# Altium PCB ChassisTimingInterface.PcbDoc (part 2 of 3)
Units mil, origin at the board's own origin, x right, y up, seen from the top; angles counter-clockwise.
Board outline 3400 x 6000 mil, 8 copper layers (Top Layer, GND, VDD, Mid-Layer 1, VCCAUX, Mid-Layer 2, MidLayer3, Bottom Layer), stack 62.1 mil thick; 229 components, 254 nets, 1249 pads, 708 vias.
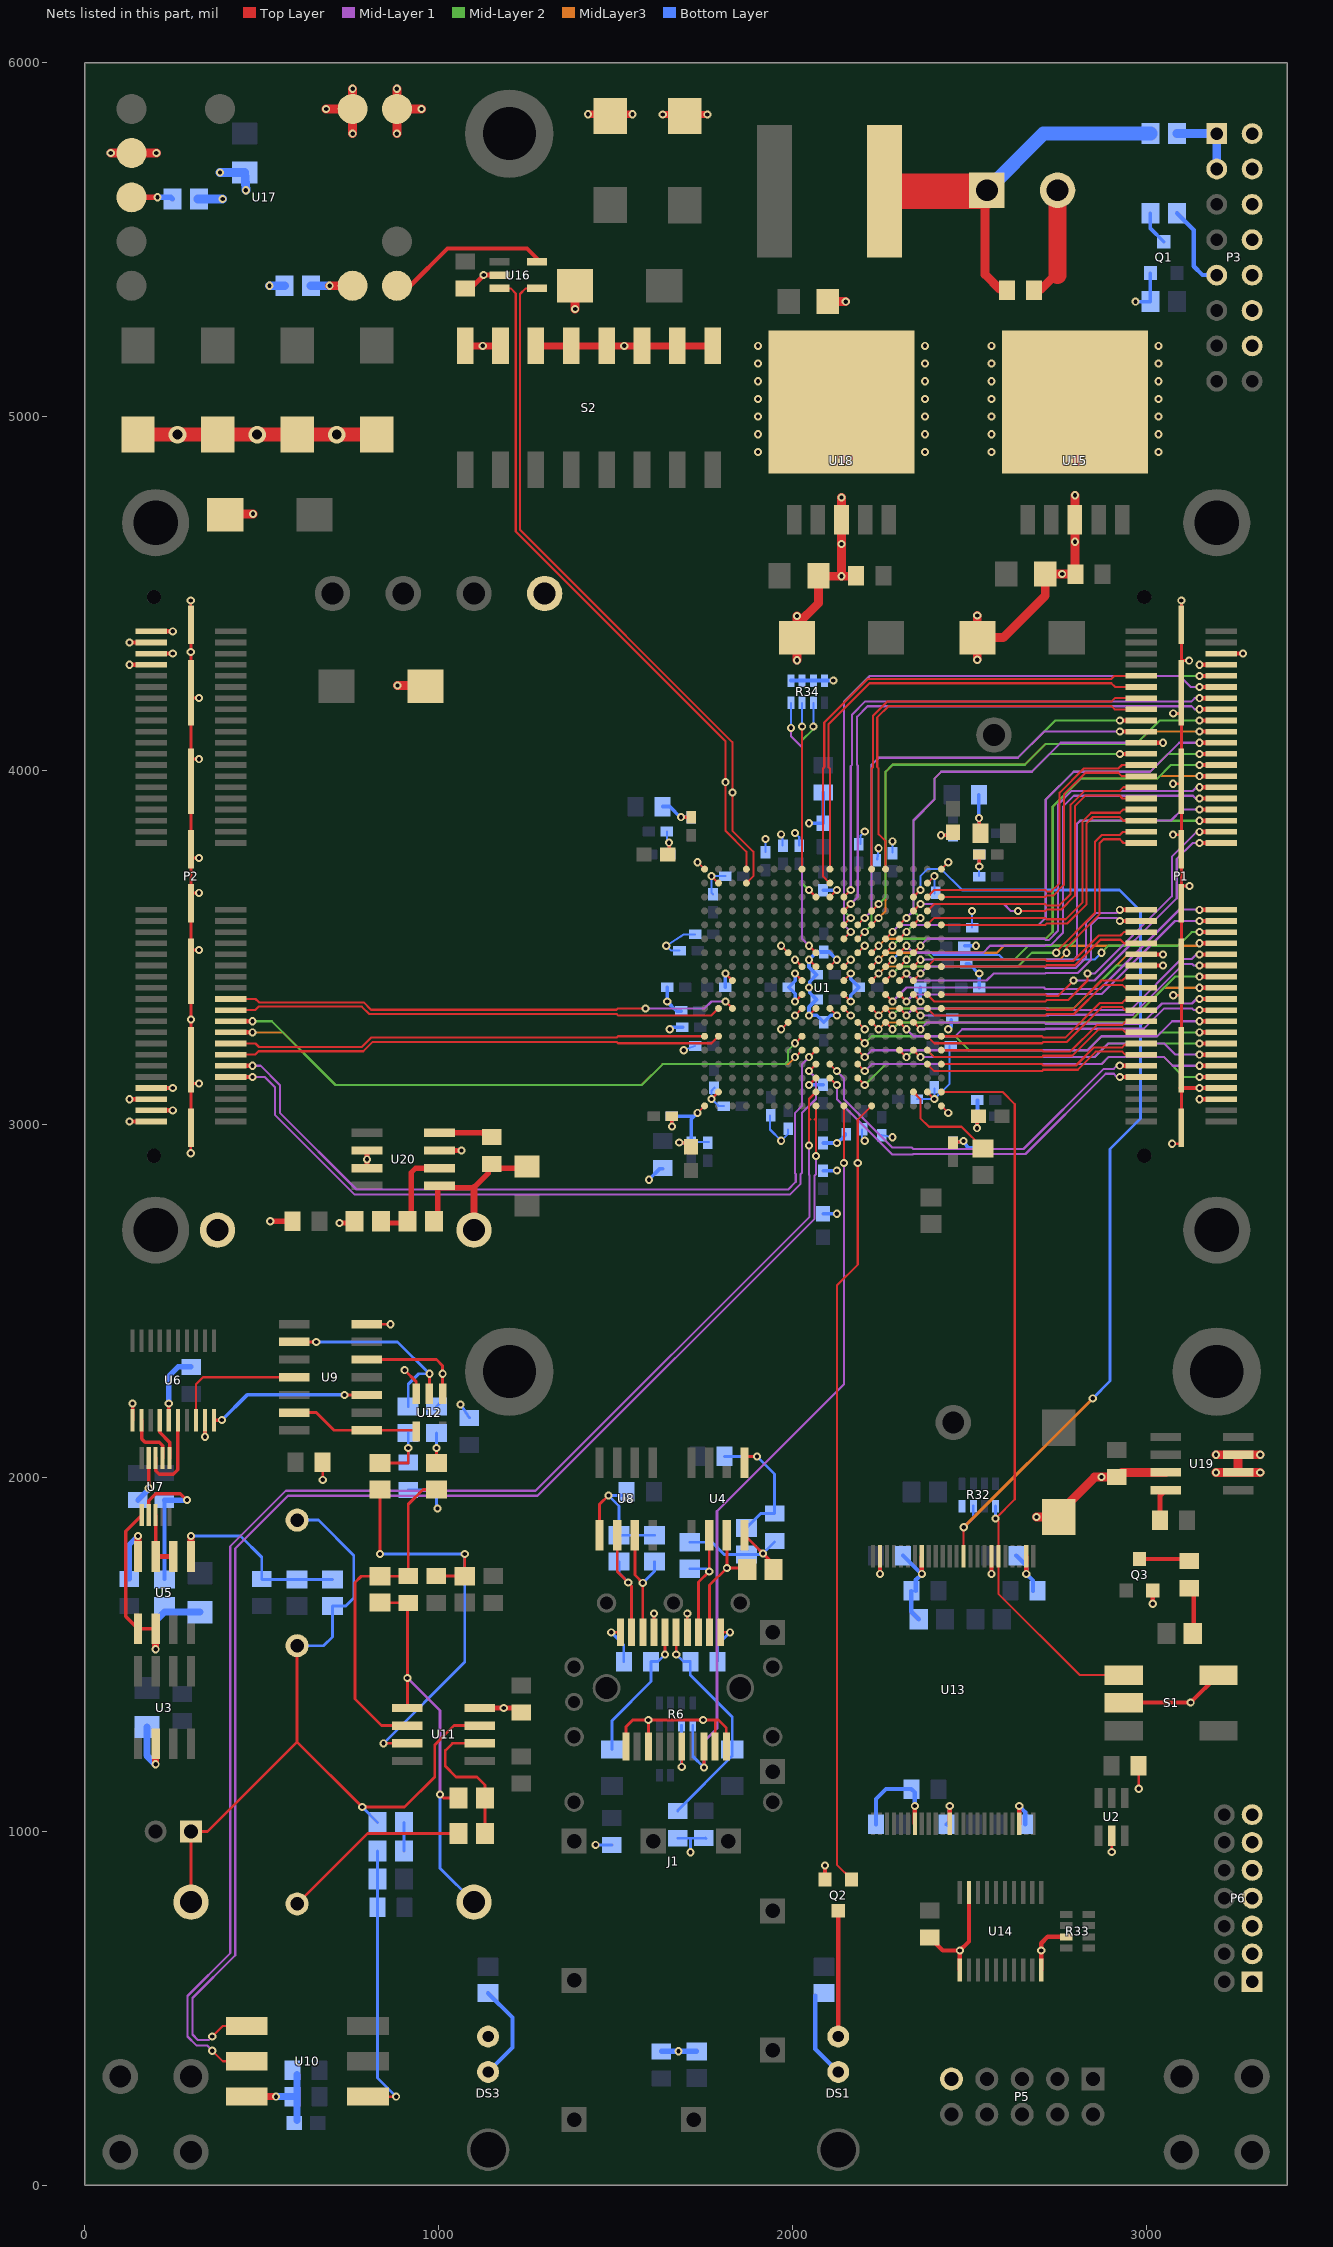
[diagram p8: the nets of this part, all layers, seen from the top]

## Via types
v1: diameter 23, hole 12, Top Layer to Bottom Layer, 669 vias
v2: diameter 23, hole 12.01, Top Layer to Bottom Layer, 33 vias
v3: diameter 50, hole 28, Top Layer to Bottom Layer, 6 vias

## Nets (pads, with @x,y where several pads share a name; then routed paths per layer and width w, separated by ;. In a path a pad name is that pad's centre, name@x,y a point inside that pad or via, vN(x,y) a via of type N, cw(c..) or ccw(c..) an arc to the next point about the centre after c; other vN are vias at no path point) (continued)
GND: C1.1 C4.1 C6.1 C7.1 C8.1 C9.1 C11.2 C12.1 C19.2 C21.1 C26.2 C27.2 C28.2 C29.2 C30.1 C31.1 C32.2 C33.1 C34.1 C35.1 C36.1 C37.1 C38.1 C39.1 C40.1 C41.2 C42.1 C43.1 C44.2 C45.2 C46.2 C47.2 C48.1 C49.2 C50.2 C51.2 C52.2 C53.2 C54.2 C55.1 C56.1 C57.2 C59.1 C62.1 C63.2 C64.2 C65.2 C66.2 C67.2 C68.2 C69.2 C70.2 C71.2 C72.2 C73.2 C74.1 C75.1 C76.1 C77.1 C78.1 C79.1 C80.1 C81.1 C82.1 C83.1 C84.1 C85.1 C86.1 C87.1 C88.1 C89.1 C90.1 C91.1 C92.1 C93.1 C94.1 C95.1 C96.1 C97.1 C98.1 C99.1 C100.1 C101.1 C102.1 C103.1 C104.1 C105.1 C106.1 C107.1 C108.1 C109.1 C110.1 C111.1 C112.1 C113.1 C114.1 C115.1 C116.1 C117.1 C118.1 C119.1 C120.1 C121.1 C122.1 C123.1 C124.1 C125.1 C126.1 C127.1 C128.1 C129.1 C130.1 C131.1 C132.1 C133.1 C134.1 C135.1 C136.1 DS3.1 J1.1 J1.3 J1.9 J1.10 J1.11 J1.14 J1.17 J1.20 P1.5 P1.7 P1.73 P1.75 P1.81 P1.82 P1.83 P1.84 P1.85 P1.86 P1.87 P1.88 P2.2 P2.4 P2.6 P2.8 P2.74 P2.76 P2.78 P2.80 P2.81 P2.82 P2.83 P2.84 P2.85 P2.86 P2.87 P2.88 P3.2 P3.4 P3.6 P3.8 P3.10 P3.12 P3.14 P5.9 P6.1 P6.3 P6.5 P6.7 P6.9 P6.11 P6.13 P7.2 Q1.2 Q2.2 Q3.2 R4.1 R8.2 R11.2 R13.1 R14.2 R30.2 R33.3 R34.5 R34.6 R34.7 R34.8 R37.1 R38.2 R40.2 S1.2 S1.5 S2.9 S2.10 S2.11 S2.12 S2.13 S2.14 S2.15 S2.16 TP9.1 TP10.1 U1.A1 U1.A18 U1.B2 U1.B17 U1.C10 U1.G7 U1.G12 U1.H8 U1.H9 U1.H10 U1.H11 U1.J3 U1.J8 U1.J11 U1.K8 U1.K11 U1.K16 U1.L8 U1.L9 U1.L10 U1.L11 U1.M7 U1.M12 U1.T9 U1.U2 U1.U17 U1.V1 U1.V18 U2.2 U4.5 U6.11 U6.15 U6.19 U7.9 U8.5 U9.7 U12.3 U13.2 U13.7 U13.17 U13.23 U13.31 U13.36 U13.46 U14.1 U14.10 U14.19 U15.3 U16.2 U17.3 U17.4 U17.7 U18.3 U19.3 U19.6 U19.7 U20.3 U20.6 U20.7 | length 18447.6
  Top Layer w6: v1(1732.3,3031.5) U1.A18@1751.99,3051.18 ; v1(1732.3,3740.16) U1.V18@1751.99,3720.47 ; v1(1771.67,3070.87) U1.B17@1791.36,3090.55 ; v1(1771.67,3700.79) U1.U17@1791.36,3681.1 ; v1(1811.04,3425.2) U1.K16@1830.73,3405.51 ; v1(1968.52,3267.72) U1.G12@1988.21,3287.4 ; v1(1968.52,3503.94) U1.M12@1988.21,3484.25 ; v1(2007.89,3307.09) U1.H11@2027.58,3326.77 ; v1(2007.89,3346.46) U1.J11@2027.58,3366.14 ; v1(2007.89,3425.2) U1.K11@2027.58,3405.51 ; v1(2007.89,3464.57) U1.L11@2027.58,3444.88 ; v1(2047.26,3110.24) U1.C10@2066.95,3129.92 ; v1(2047.26,3307.09) U1.H10@2066.95,3326.77 ; v1(2047.26,3464.57) U1.L10@2066.95,3444.88 ; U1.H9@2106.32,3326.77 v1(2126,3307.09) ; U1.L9@2106.32,3444.88 v1(2126,3464.57) ; U1.T9@2106.32,3641.73 v1(2126,3661.42) ; U1.H8@2145.69,3326.77 v1(2165.37,3307.09) ; U1.J8@2145.69,3366.14 v1(2165.37,3346.46) ; U1.K8@2145.69,3405.51 v1(2165.37,3425.2) ; U1.L8@2145.69,3444.88 v1(2165.37,3464.57) ; U1.G7@2185.06,3287.4 v1(2204.74,3267.72) ; U1.M7@2185.06,3484.25 v1(2204.74,3503.94) ; U1.J3@2342.54,3366.14 v1(2362.22,3346.46) ; U1.B2@2381.91,3090.55 v1(2401.59,3070.87) ; U1.U2@2381.91,3681.1 v1(2401.59,3700.79) ; U1.A1@2421.28,3051.18 v1(2440.96,3031.5) ; U1.V1@2421.28,3720.47 v1(2440.96,3740.16)
  Top Layer w8: v1(299.21,2917.32) P2.81@299.21,2988 ; v1(299.21,4480.31) 299.21,4412 P2.88@300,4411.22 P2.81@300,2988.78 ; P2.82@300,3114.17 v1(322.83,3114.17) ; P2.83@300,3492.13 v1(322.83,3492.13) ; P2.84@300,3653.54 v1(322.83,3653.54) ; P2.85@300,3751.97 v1(322.83,3751.97) ; P2.86@300,4031.5 v1(322.83,4031.5) ; P2.87@300,4204.72 v1(322.83,4204.72) ; v1(672.39,1994) C30.1@672.4,2044.02 ; U9.7@796.36,2434 v1(864,2434) ; v1(904,2304) 936.6,2271.4 U12.3@936.6,2237.15 ; U8.5@1455,1837.64 1455,1925 v1(1480,1950) ; v1(1488.17,1562.83) J1.20@1514.25,1562.83 ; J1.1@1530,1240 1530,1296 1549,1315 1791,1315 1813.46,1292.54 J1.10@1813.46,1240 ; J1.3@1592.99,1240 v1@1592.99,1312.99 ; J1.17@1608.74,1562.83 v1(1608.74,1616.26) ; J1.14@1703.23,1562.83 v1(1703.23,1615.77) ; J1.9@1781.97,1240 1781.97,1313.03 ; J1.11@1797.72,1562.83 v1(1824.17,1562.83) ; U4.5@1860,2060 v1(1900,2060) ; U2.2@2902.26,987.89 v1(2903,942) ; v1(2979.39,1120.61) C1.1@2979.39,1185 ; v1(3074,2944) 3098.53,2944 P1.81@3099.41,2944.88 ; v1(3076,3818) 3098,3818 3100,3820 3100,3960 3098,3962 v1(3076,3962) ; v1(3077,3364) 3099,3364 3100,3365 P1.82@3100,3181.3 ; v1(3077,4161) 3099,4161 3100,4160 P1.86@3100,3968.7 ; P1.81@3100,2988.78 3100,3046 ; 3100,3047 P1.82@3100,3100 ; P1.83@3100,3431.3 P1.84@3100,3623.83 ; P1.85@3100,3776.17 3100,3675 3102,3673 v1(3123,3673) ; P1.87@3100,4218.7 v1(3100,4480) ; P1.87@3100,4310 v1(3122,4310)
  Top Layer w10: U6.11@134.84,2162.8 v2(134.84,2209.84) ; v2(180.32,1970.31) U7.9@180.32,2055.71 ; U6.15@237.2,2162.8 v2(237.2,2209.84) ; v2(339.57,2115.75) U6.19@339.57,2162.8 ; C117.1@1647.52,3761.88 1651.65,3766.01 v1(1651.65,3795.47) ; v1(1659.65,2993.29) C116.1@1659.65,3021.88 ; v1(1680.47,2947.47) 1701.93,2947.47 C108.1@1714.06,2935.35 ; v1(1685.47,3867.47) C125.1@1714.06,3867.47 ; v1(2420.47,3816.29) 2445.93,3816.29 C126.1@2454.06,3824.42 ; C107.1@2454.06,2947.47 v1(2484.29,2951.9) ; v1(2522.47,2988.29) 2522.47,3018.17 C135.1@2526.18,3021.88 ; C82.1@2528.12,3826.43 v1(2528.12,3864.74) ; v1(2528.47,3728.29) C134.1@2528.47,3761.88
  Top Layer w12: v1(126.02,3007.1) P2.2@187.22,3007.1 ; v1(126.02,3070.08) P2.6@187.22,3070.08 ; v1(126.02,4298.42) P2.74@187.22,4298.42 ; v1(126.02,4361.42) P2.78@187.22,4361.42 ; P2.4@187.22,3038.58 v1(248.42,3038.6) ; P2.8@187.22,3101.58 v1(248.42,3101.58) ; P2.76@187.22,4329.92 v1(248.42,4329.92) ; P2.80@187.22,4392.9 v1(248.42,4392.9) ; Q2.2@2092.6,864.29 v1(2092.6,903.4) ; v1(2248.11,1728.15) U13.23@2248.11,1777.79 ; U13.31@2346.54,1021.89 v1(2346.54,1071.53) ; v1(2366.22,1728.15) U13.17@2366.22,1777.79 ; C32.2@2388.78,699.61 2425.24,663.15 v2(2473.62,663.15) ; U13.36@2444.96,1021.89 v1(2444.96,1071.53) ; U14.1@2473.62,608.74 v2(2473.62,663.15) ; U14.19@2499.21,827.24 2499.21,688.74 v2(2473.62,663.15) ; v1(2563.07,1728.15) U13.7@2563.07,1777.79 ; U13.46@2641.81,1021.89 v1(2641.81,1071.53) ; v1(2661.5,1728.15) U13.2@2661.5,1777.79 ; U14.10@2703.94,608.74 2703.94,683.94 2722.01,702.01 R33.3@2775,702.01 ; S1.5@2937.32,1364.25 v1(3126.3,1364.25) S1.2@3205.04,1442.99 ; v1(3019.21,1643.44) Q3.2@3019.21,1681.55 ; P1.82@3100,3100 3098.42,3101.58 P1.7@3209.62,3101.58 ; v1(3151.58,3070.08) P1.5@3212.78,3070.08 ; v1(3151.58,4298.42) P1.73@3212.78,4298.42 ; P1.75@3212.78,4329.92 v1(3273.98,4329.92)
  Top Layer w14: C100.1@1075,5361.61 1089.02,5361.61 v1(1127.4,5400) ; v1@1126.42,5400.98 v1(1127.4,5400) ; U16.2@1171.85,5400 v1(1127.4,5400)
  Top Layer w15: v1(524.02,2725) C62.1@586.61,2725 ; v1(720,2720) R40.2@762.6,2720 ; U20.7@797.64,2875 U20.6@797.64,2925 ; U20.3@1002.36,2925 v1(1065,2925)
  Top Layer w20: S2.16@1075,5200 S2.15@1175,5200 ; S2.14@1275,5200 S2.9@1775,5200 ; v2(1422.37,5854.83) v2(1548.35,5854.83) ; v2(1633.86,5854.33) v2(1759.84,5854.33)
  Top Layer w25: v1(73,5745) v1(202,5745) ; C64.2@399.02,4725 v1(475,4725) ; v1(682,5870) U17.4@752,5870 ; v1(757,5800) v1(757,5927) ; v1(882,5800) v1(882,5927) ; U17.3@882,5870 v1(952,5870) ; v1(884.02,4240) C63.2@960,4240 ; v1(1386.02,5303.98) C53.2@1386.02,5370 ; v1(2013.02,4311.18) v1(2013.02,4436.14) ; C54.2@2013.02,4411.14 2074.12,4472.24 2074.12,4548.66 C56.1@2180.61,4548.66 ; C49.2@2100.12,5325 v1(2151,5325) ; v1(2139,4548.66) U18.3@2139,4702.32 ; U18.3@2139,4708.66 v1(2139,4771.14) ; v1(2523.02,4312.52) v1(2523.02,4437.48) ; C41.2@2524.02,4375 2596,4375 2715,4494 2715,4555 C43.1@2800.61,4555 ; C48.1@2680,5360 2703.12,5360 2737.91,5394.8 ; v1(2690.52,1889.02) C57.2@2753,1889.02 2753,1900 2854.61,2001.61 C59.1@2918,2001.61 2931.39,2015 U19.3@3055.64,2015 ; C43.1@2799,4555 U15.3@2799,4708.66 ; U15.3@2799,4715 v1(2799,4777.48) ; v1(3197.88,2015) v1(3322.84,2015) ; v1(3197.88,2065) v1(3322.84,2065) ; U19.6@3260.36,2015 U19.7@3260.36,2065
  Top Layer w40: C44.2@150,4949.02 C47.2@825,4949.02
  Top Layer w50: 2750,5400 P7.2@2750,5637
  Bottom Layer w6: C122.1@1645.67,3826.76 1645.67,3803.14 v1@1653.54,3795.27 ; C121.1@1681.1,3490.15 1657.48,3490.15 v1(1643.7,3503.93) 1692.91,3535.42 C86.1@1724.41,3535.42 ; v1(1692.91,3208.65) C85.1@1724.41,3220.46 ; C106.1@1716.54,2948.81 C131.1@1763.78,2948.81 ; C66.2@1775.59,3649.6 1771.65,3653.53 v1(1771.67,3700.79) C70.2@1811.02,3700.78 ; C65.2@1779.53,3102.35 1771.65,3094.48 v1(1771.67,3070.87) 1791.34,3051.17 C69.2@1807.09,3051.17 ; C87.1@1924.21,3768.69 v1(1924.21,3806.1) ; C84.1@1937.01,3023.61 1937.01,2984.24 v1(1968.5,2952.75) 1988.19,2972.43 C130.1@1988.19,2984.24 ; v1(1968.5,3818.89) v1@1970.87,3819.68 ; C110.1@1972.44,3787.39 v1@1972.44,3822.83 ; v1(2007.87,3822.83) 2019.69,3811.02 C111.1@2019.69,3787.39 ; C92.1@2087.06,3661.29 C92.1@2087.18,3661.42 ; C112.1@2192.91,3791.33 2192.91,3814.95 v1(2204.73,3826.76) ; C83.1@2196.85,2984.24 2196.85,2960.62 v1(2204.73,2952.75) ; C88.1@2240.16,3748.02 v1(2244.09,3779.53) ; C128.1@2251.97,2968.5 v1(2283.46,2962.6) ; C67.2@2283.47,3767.71 v1(2283.46,3799.21) ; C72.2@2352.36,3070.86 v1(2401.59,3070.87) ; C68.2@2401.58,3100.39 v1(2401.59,3070.87) ; C71.2@2401.58,3651.57 v1(2401.59,3700.79) ; C90.1@2444.88,3220.46 2444.88,3114.16 v1(2401.59,3070.87) ; C89.1@2507.87,3555.11 v1(2507.87,3602.35) ; C113.1@2527.56,3700.78 v1@2527.56,3728.34
  Bottom Layer w8: C21.1@914,1965.61 C19.2@994,1965.61 994,1915.89 v1(996.91,1912.98) ; v1(1062,2207) C31.1@1087,2169.39 ; v1(1444,962) C6.1@1490,961.61 ; v1(1488.17,1562.83) 1523.61,1527.39 C9.1@1523.61,1480 ; C26.2@1530,1950 v1(1480,1950) 1510,1920 R13.1@1510,1837.4 R14.2@1610,1837.4 ; C8.1@1676,980.61 C7.1@1753.39,980.61 ; v1(1712,941) 1712,980.61 ; C7.1@1754.39,981.61 C7.1@1756,980 ; C4.1@1788.39,1480 1788.39,1527.06 v1(1824.17,1562.83) ; C27.2@1808.39,2060 v1(1900,2060) 1950,2010 C12.1@1950,1898.39 1910.98,1898.39 R11.2@1870,1857.4
  Bottom Layer w10: v1(1594.49,2842.51) 1625.99,2874.01 C109.1@1633.86,2874.01 ; C118.1@1633.86,3897.63 1653.54,3897.63 v1@1685.04,3866.13 ; v1@1645.67,3346.45 1673.23,3318.89 C120.1@1686.02,3318.89 ; v1(1646.46,3346.46) C96.1@1646.47,3386.88 ; C114.1@1651.65,3761.88 v1@1651.65,3795.27 ; v1(1653.54,3267.71) 1659.45,3273.61 C119.1@1689.96,3273.61 ; v1(1659.65,2993.29) C115.1@1659.65,3021.88 1722.69,3021.88 ; v1(1680.47,2947.47) C106.1@1714.06,2947.47 1714.06,3013.25 v1(1732.3,3031.5) ; v1(1685.47,3867.47) C124.1@1714.06,3867.47 ; C93.1@1810.65,3386.88 1811.04,3387.27 v1(1811.04,3425.2) ; v1(2007.89,3346.46) 2007.89,3368.64 C74.1@1989.65,3386.88 2007.89,3405.13 v1(2007.89,3425.2) ; v1@2047.5,3110.47 C91.1@2087.06,3110.47 ; v1@2047.59,3850.35 C98.1@2088.06,3850.35 C99.1@2088.06,3937.5 ; C73.2@2087.06,2746.35 v1@2126.47,2746.35 ; C80.1@2087.06,2868.47 v1@2126.47,2868.47 ; C95.1@2087.06,2946.29 v1(2126,2946.29) ; C92.1@2087.18,3661.42 v1(2126,3661.42) ; v1@2125.98,2944.87 2149.61,2968.5 C129.1@2149.61,2972.43 ; v1(2126,3307.09) 2108.67,3307.09 C77.1@2089.06,3287.47 2069.44,3307.09 v1(2047.26,3307.09) 2047.26,3330.68 C79.1@2068.47,3351.88 2049.06,3371.29 2049.06,3402.47 C78.1@2068.47,3421.88 2047.26,3443.09 v1(2047.26,3464.57) 2068.98,3486.29 2104.28,3486.29 v1(2126,3464.57) ; v1(2165.37,3346.46) 2165.37,3363.79 C75.1@2188.47,3386.88 2165.37,3409.98 v1(2165.37,3425.2) ; C94.1@2361.47,3385.88 2362.22,3385.13 v1(2362.22,3346.46) ; v1(2420.47,3816.29) C123.1@2454.06,3816.29 ; v1(2440.95,3267.71) 2448.82,3275.58 C103.1@2448.82,3295.27 ; C105.1@2454.06,2947.47 v1(2484.29,2951.9) 2496.06,2933.06 C136.1@2539.37,2933.06 ; C101.1@2488.19,3503.93 v1(2519.69,3503.93) ; C102.1@2492.13,3452.75 2500,3452.75 v1@2527.56,3425.19 ; v1(2522.47,2988.29) C132.1@2522.47,3021.88 ; C132.1@2523.62,3019.68 C104.1@2523.62,3066.92 ; v1@2527.56,3865.15 C127.1@2527.56,3931.09 ; v1(2528.12,3864.74) C81.1@2528.47,3821.88 ; v1(2528.47,3728.29) C133.1@2528.47,3761.88 ; C97.1@2528.65,3385.88 v1@2528.65,3424.47 ; v2(2970,5325) R4.1@3012.6,5325 Q1.2@3012.6,5405.71
  Bottom Layer w12: R34.5@1996.42,4253.54 v1@2116,4253.54 ; C36.1@2236.42,1019.84 2236.42,1091.46 2264.8,1119.84 C40.1@2336.42,1119.84 2346.54,1109.72 v1(2346.54,1071.53) ; C34.1@2313.19,1779.84 2364.88,1728.15 v1(2366.22,1728.15) 2349.21,1711.14 C39.1@2349.21,1679.84 ; C39.1@2336.42,1679.84 2336.42,1620.83 R30.2@2357.4,1599.84 ; C37.1@2436.42,1019.84 2444.96,1028.39 v1(2444.96,1071.53) ; C33.1@2633.19,1779.84 2661.5,1751.53 v1(2661.5,1728.15) 2680.39,1709.25 C38.1@2680.39,1679.84 ; v1(2641.81,1071.53) 2658.39,1054.96 C35.1@2658.39,1020 ; v1(3151.58,3070.08) v1@3152.49,3070.99
  Bottom Layer w15: C28.2@150,1936.61 180.32,1966.93 v2(180.32,1970.31) ; v2(237.2,2209.84) 237.2,2287.2 263.39,2313.39 C29.2@300,2313.39 ; C11.2@1630,378.39 R8.2@1729.02,378.39
  Bottom Layer w25: R38.2@319.4,5615 v1(389.4,5615) ; v1(382,5689.88) C50.2@452,5689.88 v1(455,5640) ; v1(522,5370) R37.1@564.6,5370
  other v1: 1678,378.39 2703.94,663.15 1593,1315 1748,1315 2874,2001.61 2126,2746.35 2126,2868.47 797.64,2900 3151.58,3101.58 300,3295.28 2047.24,3385.83 2528.65,3425.2 2047.26,3850.35 2116,4254 299.21,4334.65 2762.93,4555.02 2139,4639.84 2799,4646.18 1903,4900 2375,4900 2563,4900 3035,4900 1903,4950 2375,4950 2563,4950 3035,4950 1903,5000 2375,5000 2563,5000 3035,5000 1903,5050 2375,5050 2563,5050 3035,5050 1903,5100 2375,5100 2563,5100 3035,5100 1903,5150 2375,5150 2563,5150 3035,5150 1125,5200 1525,5200 1903,5200 2375,5200 2563,5200 3035,5200
  other v3: 262,4949.02 487,4949.02 712,4949.02
HSWAP: R35.1 U1.B3 | length 294.8
  Top Layer w6: U1.B3@2342.54,3090.55 2362.22,3070.87 2362.22,3016.34 2386.44,2992.12 2478.35,2992.12 R35.1@2539.37,2931.09
HWRESET: R32.4
INIT_B: R32.3 U1.T3 U13.11 | length 2849.2
  Top Layer w6: U1.T3@2342.54,3641.73 v1(2362.22,3661.42) ; U13.11@2484.33,1777.79 2484.33,1859.37 v1(2484.8,1859.84)
  MidLayer3 w8: v1(2484.8,1859.84) v1(2849.37,2224.41)
  Bottom Layer w6: v1(2362.22,3661.42) 2362.22,3700.8 2381.89,3720.47 2421.26,3720.47 2480.31,3661.42
  Bottom Layer w8: 2480.31,3661.42 2925.2,3661.42 2984.25,3602.36 2984.25,3015.75 2898,2929.5 2898,2273.04 v1(2849.37,2224.41) ; v1(2484.8,1859.84) 2511.81,1886.85 R32.3@2511.81,1919.84
LED: Q2.1 U1.A6 | length 2244.8
  Top Layer w5.98: 2185.04,2866.14 v1(2185.04,2889.76)
  Top Layer w6: Q2.1@2167.4,864.29 2125.98,905.71 2125.98,2543.3 2185.04,2602.36 2185.04,2846.45 2185.04,2866.14 ; v1(2185.04,2889.76) 2185.04,3011.79 U1.A6@2224.43,3051.18
LOS: J1.8 R6.1 U1.A8 | length 2226.7
  Top Layer w6: v1(2145.67,2889.76) U1.A8@2145.67,3051.18
  Top Layer w8: v1(1750.47,1180.47) J1.8@1750.47,1240
  Mid-Layer 1 w6: 1787.01,1905 2145.67,2263.66 2145.67,2846.45 2145.66,2866.14 v1(2145.67,2889.76)
  Mid-Layer 1 w8: v1(1750.47,1180.47) 1750.47,1254.47 1787,1291 1787,1905
  Bottom Layer w8: R6.1@1718.5,1300 1718.5,1212.44 v1(1750.47,1180.47)
M0: R34.4 U1.M10 | length 735.5
  Top Layer w6: v1(2047.26,3503.94) U1.M10@2066.95,3484.25
  Mid-Layer 1 w6: v1(1996.42,4120.03) 1996.42,4096.09 2027.57,4064.94 2027.57,3523.62 v1(2047.26,3503.94)
  Bottom Layer w6: v1(1996.42,4120.03) R34.4@1996.42,4190.54
M1: R34.3 U1.V11 | length 470.2
  Top Layer w6: U1.V11@2027.58,3720.47 2027.58,4123.2 v1(2027.91,4123.54)
  Bottom Layer w6: v1(2027.91,4123.54) R34.3@2027.91,4190.54
M2: R34.2 U1.T10 | length 578.3
  Top Layer w6: v1(2047.26,3661.42) U1.T10@2066.95,3641.73
  Mid-Layer 2 w6: v1(2047.26,3661.42) 2027.57,3681.1 2027.57,4084.64 2059.42,4116.49 v1(2059.42,4124.06)
  Bottom Layer w6: v1(2059.42,4124.06) R34.2@2059.41,4190.54
MON: C23.2 R23.2 R24.1 U5.5 | length 544.5
  Top Layer w20: U5.5@300,1777.36 v2(300,1835)
  Bottom Layer w8: v2(300,1835) 440,1835 500,1775 C23.2@500,1713.39 500.98,1712.4 R23.2@700,1712.4
NetC4_2: C4.2 C8.2 J1.15 L1.1 | length 646.3
  Top Layer w8: v1(1671.73,1500.27) J1.15@1671.73,1562.83
  Bottom Layer w8: v1(1671.73,1500.27) 1692,1480 C4.2@1711.61,1480 1711.61,1442.39 1830,1324 1830,1213 1676,1059 C8.2@1676,1057.39
NetC9_2: C9.2 J1.16 L2.1 | length 405.4
  Top Layer w8: v1(1640.24,1500.24) J1.16@1640.24,1562.83
  Bottom Layer w8: L2.1@1490,1231.18 1490,1313 1600.39,1423.39 C9.2@1600.39,1480 1620,1480 v1(1640.24,1500.24)
NetC10_2: C10.2 R10.2 U5.1 U5.2 U7.1 | length 677.9
  Top Layer w10: U7.1@160.63,1894.29 115,1848.66 115,1607.64 U5.1@150,1572.64 U5.2@200,1572.64
  Top Layer w20: v2(200,1515) U5.2@200,1572.64
  Bottom Layer w20: v2(200,1515) 200,1594.88 225,1619.88 C10.2@325,1619.88
NetC12_2: C12.2 R9.1 R11.1 R12.1 U4.4 | length 401.1
  Top Layer w8: U4.4@1865,1837.64 1947.4,1755.24 R12.1@1947.4,1740
  Bottom Layer w8: R9.1@1710,1817.4 1772.6,1817.4 1807.4,1782.6 1913.96,1782.6 C12.2@1950,1818.64
  other v1: 1917,1785.64
NetC13_1: C13.1 R10.1 U7.2 | length 452.5
  Top Layer w10: U7.2@180.32,1894.29 180.32,1935.31 200,1955 270,1955 v2(288.39,1936.61)
  Bottom Layer w10: R10.1@225,1712.4 C13.1@225,1936.61
  Bottom Layer w15: C13.1@225,1936.61 v2(288.39,1936.61)
NetC14_2: C14.2 C15.2 FR1.2 U10.6 | length 271.3
  Top Layer w20: U10.6@457.48,250 v2(540,250)
  Bottom Layer w20: v2(540,250) C15.2@599.41,250 ; FR1.2@599.41,182.87 C14.2@599.41,312.2
NetC16_1: C16.1 R18.2 | length 539
  Top Layer w8: C16.1@600,795 799,994 R18.2@1056.6,994
NetC16_2: C16.2 P4.1 pad.0@600,1880 R19.2 R23.1 TP2.1 U11.7 | length 2268.1
  Top Layer w8: TP2.1@300,800 P4.1@300,1000 347,1000 600,1253 ; C16.2@600,1525 600,1253 ; U11.7@1116.36,1299 1044,1299 989,1244 989,1154 904,1069 v1(784,1069) 600,1253
  Bottom Layer w8: C16.2@600,1525 675,1525 700,1550 R23.1@700,1637.6 737.6,1637.6 760,1660 760,1780 660,1880 pad.0@600,1880 ; v1(784,1069) 784,1068.6 R19.2@827.6,1025
NetC17_1: C17.1 R15.2 R22.1 TP1.1 U11.1 | length 1145.4
  Top Layer w8: R15.2@834,1646.6 913.02,1646.6 C17.1@914,1645.61 ; U11.1@911.64,1349 C17.1@911.64,1645.22 ; v1(1004,1104) 1014,1094 R22.1@1056.6,1094
  Mid-Layer 1 w8: v1(911.64,1434) 1004,1341.64 v1(1004,1104)
  Bottom Layer w8: v1(1004,1104) 1004,896 TP1.1@1100,800
NetC17_2: C17.2 R15.1 R17.2 U11.2 | length 966.2
  Top Layer w8: U11.2@911.64,1299 839,1299 764,1374 764,1704 781.4,1721.4 913.02,1721.4 C17.2@914,1722.39 914,1925 955.6,1966.6 R17.2@994,1966.6
NetC19_1: C19.1 R16.2 R17.1 | length 126.8
  Top Layer w8: R17.1@994,2041.4 v1(994,2084)
  Bottom Layer w8: C19.1@994,2042.39 R16.2@994,2126.6
NetC20_1: C20.1 R20.1 R21.1 U10.1 | length 796.7
  Top Layer w8: U10.1@800,250 v1(880,250)
  Bottom Layer w8: R20.1@827.6,945 827.6,302.4 v1(880,250)
NetC21_2: C21.2 R25.2 R26.1 | length 206.8
  Top Layer w8: R26.1@834,2041.4 914,2041.4 v1(914,2084)
  Bottom Layer w8: C21.2@914,2042.39 R25.2@914,2126.6
NetC24_2: C24.2 R26.2 R27.1 U11.3 | length 1262.1
  Top Layer w8: v1(834,1784) R26.2@834,1966.6 ; v1(844,1249) U11.3@911.64,1249 ; C24.2@994,1722.39 R27.1@1073.02,1722.39 ; R27.1@1074,1721.4 v1(1074,1784)
  Bottom Layer w8: v1(834,1784) v1(1074,1784) 1074,1479 v1(844,1249)
NetC58_2: C58.2 U19.4 | length 91.6
  Top Layer w15: C58.2@3039.61,1880 3039.61,1948.98 U19.4@3055.64,1965
NetC60_2: C60.2 U20.4 | length 146.9
  Top Layer w15: U20.4@1000,2975 1123.39,2975 C60.2@1140,2958.39
NetDS1_1: DS1.1 Q2.3 | length 355.7
  Top Layer w12: DS1.1@2130,420 Q2.3@2130,775.71
NetDS1_2: DS1.2 R5.1 | length 242.9
  Bottom Layer w12: R5.1@2065,536 2065,385 DS1.2@2130,320
NetDS2_1: DS2.1 Q3.3 | length 142.4
  Top Layer w12: Q3.3@2981.8,1770.13 3115.9,1770.13 DS2.1@3121.8,1764.23
NetDS2_2: DS2.2 R28.2 | length 120.6
  Top Layer w12: R28.2@3134.8,1562.44 DS2.2@3134.8,1683
NetDS3_2: DS3.2 R36.1 | length 279.8
  Bottom Layer w12: DS3.2@1140,320 1209,389 1209,473.6 R36.1@1140,542.6
NetJ1_12: J1.12 R12.2 U4.3 | length 347.6
  Top Layer w8: J1.12@1766.22,1562.83 1766.22,1696.22 v1(1815,1745) ; U4.3@1815,1837.64 v1(1815,1745) ; R12.2@1867.6,1745 v1(1815,1745)
NetJ1_13: J1.13 R9.2 U4.2 | length 345.5
  Top Layer w8: J1.13@1734.72,1562.83 1734.72,1704.72 v1(1765,1735) U4.2@1765,1837.64
  Bottom Layer w8: R9.2@1710,1742.6 1757.4,1742.6 v1(1765,1735)
NetJ1_18: J1.18 R14.1 U8.7 | length 357.4
  Top Layer w8: U8.7@1555,1837.64 1555,1725 v1(1577.24,1702.76) J1.18@1577.24,1562.83
  Bottom Layer w8: v1(1577.24,1702.76) 1610,1735.51 R14.1@1610,1762.6
NetJ1_19: J1.19 R13.2 U8.6 | length 361.2
  Top Layer w8: U8.6@1505,1837.64 1505,1735 1545.75,1694.25 J1.19@1545.75,1562.83
  Bottom Layer w8: R13.2@1510,1762.6 1510,1730 v1(1536.1,1703.9)
NetP3_1: P3.1 P3.3 R2.1 | length 212.6
  Bottom Layer w25: R2.1@3087.4,5800 P3.1@3200,5800 P3.3@3200,5700
NetP3_9: P3.9 R3.1 | length 245.1
  Bottom Layer w12: R3.1@3087.4,5575 3135,5527.4 3135,5425 3160,5400 P3.9@3200,5400
NetQ1_3: Q1.3 R3.2 | length 96.2
  Bottom Layer w10: R3.2@3012.6,5575 3012.6,5531.69 Q1.3@3050,5494.29
NetR16_1: R16.1 U9.5 U12.1 | length 401.5
  Top Layer w8: U9.5@796.36,2334 994,2334 1011.4,2316.6 U12.1@1011.4,2237.15
  Bottom Layer w8: R16.1@994,2201.4 1011.4,2218.8 v1(1011.4,2294)
NetR18_1: R18.1 R22.2 U11.6 | length 422.4
  Top Layer w8: U11.6@1116.36,1249 1039,1249 1019,1229 1019,1184 1049,1154 1109,1154 1131.4,1131.6 R18.1@1131.4,994
NetR19_1: R19.1 R20.2 | length 80
  Bottom Layer w8: R20.2@902.4,945 R19.1@902.4,1025
NetR25_1: R25.1 U9.9 U12.2 | length 611.5
  Top Layer w8: U9.9@591.64,2384 v1(654,2384) ; U12.2@974,2237.15 v1(974,2294)
  Bottom Layer w8: v1(654,2384) 884,2384 v1(974,2294) 944,2294 914,2264 R25.1@914,2201.4
NetR37_2: R37.2 U17.11 | length 117.6
  Top Layer w25: v1(692,5370) U17.11@757,5370
  Bottom Layer w25: R37.2@639.4,5370 v1(692,5370)
NetR38_1: R38.1 U17.8 | length 117.7
  Top Layer w15: U17.8@132,5620 v1(205,5620)
  Bottom Layer w15: v1(205,5620) 242.6,5620 R38.1@247.6,5615
NetR39_1: R39.1 R40.1 U20.2 | length 312.7
  Top Layer w15: R40.1@837.4,2720 922.6,2720 922.6,2862.6 935,2875 U20.2@1002.36,2875
NetU5_6: U5.6 U5.7 U7.3 | length 166.9
  Top Layer w10: U5.7@200,1777.36 U7.3@200,1894.29
  Top Layer w15: U5.7@200,1777.36 U5.6@250,1777.36
NetU6_12: U6.12 U7.7 | length 155.1
  Top Layer w10: U6.12@160.43,2162.8 160.43,2109.57 170,2100 210,2100 219.68,2090.31 U7.7@219.68,2055.71
NetU6_14: U6.14 U7.6 | length 118.6
  Top Layer w10: U6.14@211.61,2162.8 211.61,2128.39 239.37,2100.63 U7.6@239.37,2055.71
NetU6_16: U6.16 U7.8 | length 247.9
  Top Layer w10: U7.8@200,2055.71 200,2020 210,2010 250,2010 262.8,2022.8 U6.16@262.8,2162.8
NetU6_18: U6.18 U9.11 | length 387.1
  Top Layer w6: U6.18@313.98,2162.8 313.98,2263.98 334,2284 U9.11@591.64,2284
NetU6_20: U6.20 U9.3 | length 460.7
  Top Layer w8: v1(734,2234) U9.3@796.36,2234
  Top Layer w10: U6.20@365.16,2162.8 v2(387.2,2162.8)
  Bottom Layer w10: v2(387.2,2162.8) 458.41,2234 v1(734,2234)
NetU9_1: U9.1 U9.13 U12.4 | length 362.5
  Top Layer w8: U9.13@591.64,2184 654,2184 704,2134 U12.4@933.45,2134
NetU16_5: U16.5 U17.1 | length 485.6
  Top Layer w12: U17.1@899.6,5387.6 U17.1@882,5370 920,5370 1025,5475 1250,5475 1278.15,5446.85 U16.5@1278.15,5437.4
OSCCLK_N: U1.A10 U10.4 | length 3985.8
  Top Layer w6: v1(360,420) 390,450 U10.4@457.48,450 ; 2063.1,3012.5 2066.95,3016.34 U1.A10@2066.95,3051.18 2066.95,2958.68 ; v1(2066.93,2909.44) 2066.92,2958.66
  Mid-Layer 1 w6: 349.9,409.9 319.9,409.9 304,425.8 304,529 425,650 425,1800 574,1949 1279.71,1949 2062.99,2732.28 2062.99,2854.32 2066.93,2858.26 2066.93,2874.01 2066.93,2893.69 v1(2066.93,2909.44) ; 350,410 v1(360,420)
OSCCLK_P: U1.B10 U10.5 | length 4023.3
  Top Layer w6: v1(360,380) 390,350 U10.5@457.48,350 ; v1(2047.24,2938.97) 2047.24,2958.66 ; 2047.26,2958.68 2047.26,3070.87 U1.B10@2066.95,3090.55 ; 2047.26,3016.34 2051.1,3012.5
  Mid-Layer 1 w6: v1(360,380) 345,395 315,395 290,420 290,534.8 411,655.8 411,1805.8 568.2,1963 1273.91,1963 2048.99,2738.08 2048.99,2854.32 2047.24,2856.07 2047.24,2874.01 2047.24,2891.73 v1(2047.24,2938.97)
P10V: C2.1 C5.2 C18.2 C60.1 C61.1 R39.2 TP7.1 U3.2 U5.8 U11.8 U20.1 | length 1009.2
  Top Layer w8: C18.2@1220.61,1349 C18.2@1234,1335.61
  Top Layer w15: R39.2@997.4,2720 997.4,2820.04 1100.04,2820.04 1140,2860 1140,2881.61 1146.5,2875.12 C61.1@1260,2875.12 ; U11.8@1116.36,1349 C18.2@1220.61,1349
  Top Layer w20: U5.8@150,1777.36 v2(150,1835) ; v2(200,1190) U3.2@200,1247.64 ; TP7.1@1100,2700 1100,2820 1100.04,2820.04
  Bottom Layer w15: C5.2@125,1713.39 125,1810 v2(150,1835)
  Bottom Layer w20: C2.1@175,1294.88 175,1215 v2(200,1190)
  other v1: 1184,1349
P12V: C48.2 L3.1 P7.1 R2.2 | length 1130.8
  Top Layer w25: P7.1@2545,5637 2545,5401.88 2586.88,5360 C48.2@2610,5360
  Top Layer w100: L3.1@2260.5,5637 P7.1@2545,5637
  Bottom Layer w40: P7.1@2550,5640 2710,5800 R2.2@3012.6,5800
PROG_B: R32.1 S1.1 U1.B1 U13.6 | length 2116.7
  Top Layer w6: U1.B1@2421.28,3090.53 2594.51,3090.53 2628.94,3056.1 2628.94,1938.98 v1(2574.8,1884.84) 2582.76,1876.89 2582.76,1671.89 2812.65,1442 S1.1@2937.32,1442
  Bottom Layer w8: v1(2574.8,1884.84) R32.1@2574.8,1919.84
PWRSYNC_N: U1.U15 U16.4 | length 2001.8
  Top Layer w5.98: 1830.71,3982.28 1830.71,4005.91 1830.71,4079.29
  Top Layer w6: U16.4@1278.15,5362.6 1245.94,5362.6 1230,5346.66 1230,4680 1830.71,4079.29 ; 1830.71,3982.28 1830.71,3828.8 1889.78,3769.72 1889.78,3700.79 U1.U15@1870.1,3681.1
  other v1: 1830.71,3937.01
PWRSYNC_P: U1.V15 U16.3 | length 1950
  Top Layer w6: U16.3@1171.85,5362.6 1203.61,5362.6 1218,5348.21 1218,4675.03 1811.02,4082.01 1811.02,4005.91 1811.02,3982.28 1811.02,3828.8 1870.1,3769.72 U1.V15@1870.1,3720.47
  other v1: 1811.02,3966.54
RDY: J1.6 R6.2 | length 175.2
  Top Layer w8: v1(1687.48,1182.52) J1.6@1687.48,1240
  Bottom Layer w8: R6.2@1687.01,1300 1687.01,1182.99 v1(1687.48,1182.52)
S1_16.S1_N: P1.12 U1.D9 | length 1112.5
  Top Layer w6: U1.D9@2106.32,3169.29 v1(2126,3149.61)
  Top Layer w12: v1(2925.8,3165) P1.12@2987,3165
  Mid-Layer 1 w6: v1(2126,3149.61) 2145.69,3129.92 2145.69,3070.87 2283.48,2933.07 2303.15,2933.07 2322.83,2933.07 2338.58,2933.07 2342.52,2929.13 2653.54,2929.13 2880.41,3156 2909,3156 2918,3165 v1(2925.8,3165)
S1_16.S1_P: P1.10 U1.C9 | length 1092.1
  Top Layer w6: U1.C9@2106.32,3129.92 v1(2126,3110.24)
  Top Layer w12: v1(2926.02,3133.08) P1.10@2987.22,3133.08
  Mid-Layer 1 w6: v1(2126,3110.24) 2126,3070.85 2283.46,2913.39 2303.15,2913.39 2322.83,2913.39 2340.77,2913.39 2342.52,2915.13 2659.34,2915.13 2886.21,3142 2909,3142 2917.92,3133.08 v1(2926.02,3133.08)
S1_16.S2_N: P1.14 U1.D2 | length 639.6
  Top Layer w6: U1.D2@2381.91,3169.29 2401.59,3149.61 2677.17,3149.61 2696.85,3149.61 2705.71,3149.61 ; 2705.81,3149.61 2709.65,3153.45 2806.99,3153.45 2858.07,3204.53 2933.07,3204.53 2941.53,3196.07 P1.14@2987.22,3196.07
S1_16.S2_P: P1.16 U1.D1 | length 593.3
  Top Layer w6: U1.D1@2421.28,3169.29 2677.17,3169.29 2696.85,3169.29 2705.8,3169.29 2709.65,3165.45 2802.02,3165.45 2853.1,3216.53 2933.07,3216.53 2944.11,3227.57 P1.16@2987.22,3227.57
S1_16.S3_N: P1.20 U1.E1 | length 603.1
  Top Layer w6: U1.E1@2421.28,3208.66 2677.17,3208.66 2696.85,3208.66 2705.8,3208.66 2709.65,3204.82 2786.27,3204.82 2860.98,3279.53 2933.07,3279.53 2944.11,3290.57 P1.20@2987.22,3290.57
S1_16.S3_P: P1.18 U1.E2 | length 649.4
  Top Layer w6: U1.E2@2381.91,3208.66 2401.59,3188.98 2677.17,3188.98 2696.85,3188.98 2705.71,3188.98 ; 2705.81,3188.98 2709.65,3192.82 2791.24,3192.82 2865.95,3267.53 2933.07,3267.53 2941.53,3259.07 P1.18@2987.22,3259.07
S1_16.S4_N: P1.22 U1.F2 | length 659.2
  Top Layer w6: U1.F2@2381.91,3248.03 2401.59,3228.35 2677.17,3228.35 2696.85,3228.35 2705.71,3228.35 ; 2705.81,3228.35 2709.65,3232.19 2776.72,3232.19 2875.04,3330.51 2933.07,3330.51 2941.53,3322.05 P1.22@2987.22,3322.05
S1_16.S4_P: P1.24 U1.F1 | length 612.8
  Top Layer w6: U1.F1@2421.28,3248.03 2677.17,3248.03 2696.85,3248.03 2705.8,3248.03 2709.65,3244.19 2771.75,3244.19 2870.07,3342.51 2933.07,3342.51 2944.11,3353.55 P1.24@2987.22,3353.55
S1_16.S5_N: P1.28 U1.H1 | length 655.5
  Top Layer w6: U1.H1@2421.28,3326.77 2667.32,3326.77 ; 2618.11,3326.77 2683.07,3326.77 2706.69,3326.77 2715.65,3326.77 2719.49,3322.93 2791.43,3322.93 2874.02,3405.51 2933.07,3405.51 2944.11,3416.55 P1.28@2987.22,3416.55
S1_16.S5_P: P1.26 U1.H2 | length 652.7
  Top Layer w6: U1.H2@2381.91,3326.77 2401.59,3307.09 2637.79,3307.09 2683.07,3307.09 2706.69,3307.09 2715.55,3307.09 ; 2715.65,3307.09 2719.49,3310.93 2796.4,3310.93 2878.99,3393.51 2933.07,3393.51 2941.53,3385.05 P1.26@2987.22,3385.05
S1_16.S6_N: P1.30 U1.H5 | length 912.4
  Top Layer w6: U1.H5@2263.8,3326.77 v1(2283.48,3307.09)
  Top Layer w12: P1.30@2987.22,3448.03 v1(3048.42,3448.03)
  Mid-Layer 2 w6: v1(2283.48,3307.09) 2303.17,3326.77 2683.07,3326.77 2704.72,3326.77 2795.28,3326.77 2916.54,3448.03 v1(3048.42,3448.03)
S1_16.S6_P: P1.32 U1.H6 | length 964.8
  Top Layer w6: U1.H6@2224.43,3326.77 v1(2244.11,3307.09)
  Top Layer w12: P1.32@2987.22,3479.53 v1(3048.42,3479.53)
  MidLayer3 w6: v1(2244.11,3307.09) 2263.8,3326.77 2683.07,3326.77 2704.72,3326.77 2795.28,3326.77 2948.04,3479.53 v1(3048.42,3479.53)
S1_16.S7_N: P1.36 U1.L2 | length 648.9
  Top Layer w6: U1.L2@2381.91,3444.88 2401.59,3464.57 2637.79,3464.57 2683.07,3464.57 2706.39,3464.57 2715.34,3464.57 2719.18,3460.72 2794.15,3460.72 2866.42,3533 2928,3533 2937.53,3542.53 P1.36@2987.22,3542.53
S1_16.S7_P: P1.34 U1.L1 | length 601.5
  Top Layer w6: U1.L1@2421.28,3444.88 2667.32,3444.88 2683.07,3444.88 2706.39,3444.88 2715.24,3444.88 ; 2715.34,3444.88 2719.18,3448.72 2799.12,3448.72 2871.39,3521 2928,3521 2937.97,3511.03 P1.34@2987.22,3511.03
S1_16.S8_N: P1.38 U1.K4 | length 835
  Top Layer w6: U1.K4@2303.17,3405.51 v1(2322.85,3425.2)
  Top Layer w12: v1(2926.02,3574.02) P1.38@2987.22,3574.02
  Mid-Layer 1 w6: v1(2322.85,3425.2) 2342.54,3405.51 2549.21,3405.51 2568.9,3425.2 2677.17,3425.2 2696.85,3425.2 2714.79,3425.2 2716.54,3426.94 2806.87,3426.94 2844.49,3464.57 2844.49,3562.99 2864.17,3582.68 2917.36,3582.68 v1(2926.02,3574.02)
S1_16.S8_P: P1.40 U1.K3 | length 788.4
  Top Layer w6: U1.K3@2342.54,3405.51 v1(2362.22,3425.2)
  Top Layer w12: v1(2926.02,3605.52) P1.40@2987.22,3605.52
  Mid-Layer 1 w6: v1(2362.22,3425.2) 2381.91,3444.88 2677.17,3444.88 2696.85,3444.88 2712.6,3444.88 2716.54,3440.94 2801.07,3440.94 2830.49,3470.37 2830.49,3568.79 2858.37,3596.68 2917.18,3596.68 v1(2926.02,3605.52)
S1_16.S9_N: P1.44 U1.K5 | length 1021
  Top Layer w6: U1.K5@2263.8,3405.51 v1(2283.48,3425.2) ; v1(2746.06,3484.25) 2743.28,3484.25 2856,3596.97 2856,3798.17 2874.85,3817.02 2926,3817.02 2934.97,3825.98 P1.44@2987.22,3825.98
  Mid-Layer 2 w6: v1(2283.48,3425.2) 2303.17,3444.88 2637.8,3444.88 2677.17,3484.25 2696.85,3484.25 v1(2746.06,3484.25)
S1_16.S9_P: P1.42 U1.K6 | length 1059.5
  Top Layer w6: U1.K6@2224.43,3405.51 v1(2244.11,3425.2) ; v1(2775.59,3484.25) 2775.59,3499.59 2868,3592 2868,3793.2 2879.82,3805.02 2926,3805.02 2936.53,3794.48 P1.42@2987.22,3794.48
  MidLayer3 w6: v1(2244.11,3425.2) 2263.8,3444.88 2637.8,3444.88 2657.48,3464.57 2677.17,3464.57 2696.85,3464.57 2755.91,3464.57 v1(2775.59,3484.25)
S1_16.S10_N: P1.46 U1.P1 | length 833.2
  Top Layer w6: U1.P1@2421.28,3562.99 2637.79,3562.99 2683.07,3562.99 2706.69,3562.99 2715.55,3562.99 ; 2715.65,3562.99 2719.49,3566.83 2729.33,3566.83 ; 2726.85,3566.83 2777.8,3566.83 2832,3621.03 2832,3850.03 2849.97,3868 2926,3868 2936.53,3857.47 P1.46@2987.22,3857.47
S1_16.S10_P: P1.48 U1.P2 | length 877.7
  Top Layer w6: U1.P2@2381.91,3562.99 2401.59,3582.68 2667.32,3582.68 2683.07,3582.68 2706.69,3582.68 2715.65,3582.68 2719.49,3578.83 2772.83,3578.83 2820,3626 2820,3855 2845,3880 2926,3880 2934.97,3888.97 P1.48@2987.22,3888.97
S1_16.S11_N: P1.52 U1.R2 | length 901.2
  Top Layer w6: U1.R2@2381.91,3602.36 2401.59,3622.05 2667.32,3622.05 2683.07,3622.05 2706.69,3622.05 2715.65,3622.05 2719.49,3618.2 2754.77,3618.2 2787,3650.43 2787,3902.97 2825.03,3941 2925,3941 2935.97,3951.97 P1.52@2987.22,3951.97
S1_16.S11_P: P1.50 U1.R3 | length 947.7
  Top Layer w6: U1.R3@2342.54,3602.36 v1(2362.22,3622.05) ; v1(2637.8,3602.36) 2683.07,3602.36 2706.69,3602.36 2715.55,3602.36 ; 2715.65,3602.36 2719.49,3606.2 2759.75,3606.2 2799,3645.46 2799,3898 2830,3929 2925,3929 2933.53,3920.47 P1.50@2987.22,3920.47
  Mid-Layer 1 w6: v1(2362.22,3622.05) 2598.43,3622.05 2618.11,3602.36 v1(2637.8,3602.36)
S1_16.S12_N: P1.54 U1.T1 | length 865.2
  Top Layer w6: U1.T1@2421.28,3641.73 2677.17,3641.73 2706.69,3641.73 2715.55,3641.73 ; 2715.65,3641.73 2719.49,3645.57 2737.35,3645.57 2767.91,3676.13 2767.91,3932.04 2828.87,3993 2922,3993 2931.55,3983.45 P1.54@2987.22,3983.45
S1_16.S12_P: P1.56 U1.T2 | length 913
  Top Layer w6: U1.T2@2381.91,3641.73 2401.59,3661.42 2677.17,3661.42 2706.69,3661.42 2715.65,3661.42 2719.49,3657.57 2732.38,3657.57 2755.91,3681.1 2755.91,3937.01 2823.9,4005 2922,4005 2931.95,4014.95 P1.56@2987.22,4014.95
S1_16.S13_N: P1.60 U1.P4 | length 1204.3
  Top Layer w6: U1.P4@2303.17,3562.99 v1(2322.85,3582.68)
  Top Layer w12: P1.60@2987.22,4077.95 v1(3048.42,4077.95)
  Mid-Layer 1 w6: v1(2322.85,3582.68) 2342.52,3602.35 2342.52,3858.27 2401.57,3917.32 2401.57,3956.69 2401.57,3976.38 2421.26,3996.06 2677.17,3996.06 2759.05,4077.95 v1(3048.42,4077.95)
S1_16.S13_P: P1.58 U1.P3 | length 1068.8
  Top Layer w6: U1.P3@2342.54,3562.99 v1(2362.22,3582.68)
  Top Layer w12: v1(2926.02,4046.45) P1.58@2987.22,4046.45
  Mid-Layer 2 w6: v1(2362.22,3582.68) 2342.52,3602.38 2342.52,3858.27 2401.57,3917.32 2401.57,3956.69 2401.57,3976.38 2421.26,3996.06 2677.17,3996.06 2727.55,4046.45 v1(2926.02,4046.45)
S1_16.S14_N: P1.62 U1.P7 | length 1270.7
  Top Layer w6: U1.P7@2185.06,3562.99 v1(2204.74,3582.68)
  Top Layer w12: v1(2926.02,4109.43) P1.62@2987.22,4109.43
  Mid-Layer 1 w6: v1(2204.74,3582.68) 2224.41,3602.35 2224.41,3976.38 2224.41,3996.06 2224.41,4015.75 2244.09,4035.43 2637.8,4035.43 2711.8,4109.43 v1(2926.02,4109.43)
S1_16.S14_P: P1.64 U1.N7 | length 1323.1
  Top Layer w6: U1.N7@2185.06,3523.62 v1(2204.74,3543.31)
  Top Layer w12: v1(2926.02,4140.93) P1.64@2987.22,4140.93
  Mid-Layer 2 w6: v1(2204.74,3543.31) 2224.41,3562.98 2224.41,3976.38 2224.41,3996.06 2224.41,4015.75 2244.09,4035.43 2637.8,4035.43 2743.3,4140.93 v1(2926.02,4140.93)
S1_16.S15_N: P1.68 U1.V6 | length 1215.2
  Top Layer w6: U1.V6@2224.43,3720.47 2224.43,3976.36 2224.41,3996.06 2224.41,4005.02 2228.25,4008.86 2228.25,4154.67 2267.58,4194 2902,4194 2911.93,4203.93 P1.68@2987.22,4203.93
S1_16.S15_P: P1.66 U1.V5 | length 1203.2
  Top Layer w6: 2244.09,4004.92 2244.09,3996.06 2244.09,3976.38 2244.09,3818.9 2263.8,3799.2 U1.V5@2263.8,3720.47 ; 2244.09,4005.02 2240.25,4008.86 2240.25,4149.7 2272.55,4182 2902,4182 2911.57,4172.43 P1.66@2987.22,4172.43
S1_16.S16_N: P1.70 U1.V9 | length 1348.2
  Top Layer w6: U1.V9@2106.32,3720.47 2106.32,3976.38 2106.3,3996.06 2106.3,4004.92 ; 2106.3,4005.02 2102.46,4008.86 2102.46,4130.02 2218.44,4246 2902,4246 2912.58,4235.42 P1.70@2987.22,4235.42
S1_16.S16_P: P1.72 U1.U9 | length 1415.1
  Top Layer w6: U1.U9@2106.32,3681.1 2086.61,3700.79 2086.61,3976.38 2086.61,3996.06 2086.61,4005.02 2090.46,4008.86 2090.46,4134.99 2213.47,4258 2902,4258 2910.92,4266.92 P1.72@2987.22,4266.92
S17_32.S17_N: P1.11 U1.D7 | length 1062.3
  Top Layer w6: U1.D7@2185.06,3169.29 v1(2204.74,3149.61)
  Top Layer w12: v1(3151.58,3164.58) P1.11@3212.78,3164.58
  Mid-Layer 1 w6: v1(2204.74,3149.61) 2224.43,3169.29 2677.17,3169.29 2696.85,3169.29 2874.02,3169.29 2893.7,3188.98 3051.18,3188.98 3075.57,3164.58 v1(3151.58,3164.58)
S17_32.S17_P: P1.9 U1.C7 | length 1091.6
  Top Layer w6: U1.C7@2185.06,3129.92 v1(2204.74,3110.24)
  Top Layer w12: v1(3151.58,3133.08) P1.9@3212.78,3133.08
  Mid-Layer 2 w6: v1(2204.74,3110.24) 2263.79,3169.28 2677.16,3169.28 2696.85,3169.29 2874.02,3169.29 2893.7,3188.98 3051.18,3188.98 3107.07,3133.08 v1(3151.58,3133.08)
S17_32.S18_N: P1.13 U1.E3 | length 907.4
  Top Layer w6: U1.E3@2342.54,3208.66 v1(2362.22,3188.98)
  Top Layer w12: v1(3151.58,3196.07) P1.13@3212.78,3196.07
  Mid-Layer 1 w6: v1(2362.22,3188.98) 2677.17,3188.98 2696.85,3188.98 2854.33,3188.98 2892.92,3227.57 3051.96,3227.57 3083.46,3196.07 v1(3151.58,3196.07)
S17_32.S18_P: P1.15 U1.E4 | length 950.1
  Top Layer w6: U1.E4@2303.17,3208.66 v1(2322.85,3188.98)
  Top Layer w12: v1(3151.58,3227.57) P1.15@3212.78,3227.57
  Mid-Layer 2 w6: v1(2322.85,3188.98) 2342.54,3208.66 2381.89,3208.66 2401.57,3188.98 2677.17,3188.98 2696.85,3188.98 2854.33,3188.98 2892.92,3227.57 v1(3151.58,3227.57)
S17_32.S19_N: P1.19 U1.E7 | length 1078
  Top Layer w6: U1.E7@2185.06,3208.66 v1(2204.74,3188.98)
  Top Layer w12: v1(3151.58,3290.57) P1.19@3212.78,3290.57
  Mid-Layer 1 w6: v1(2204.74,3188.98) 2224.43,3208.66 2677.17,3208.66 2696.85,3208.66 2834.65,3208.66 2874.02,3248.03 3031.5,3248.03 3074.03,3290.57 v1(3151.58,3290.57)
S17_32.S19_P: P1.17 U1.F7 | length 1081.2
  Top Layer w6: U1.F7@2185.06,3248.03 v1(2204.74,3228.35)
  Top Layer w12: v1(3151.58,3259.07) P1.17@3212.78,3259.07
  Mid-Layer 2 w6: v1(2204.74,3228.35) 2224.43,3248.03 2460.63,3248.03 2500,3208.66 2677.17,3208.66 2696.85,3208.66 2834.65,3208.66 2874.02,3248.03 3031.5,3248.03 3042.53,3259.07 v1(3151.58,3259.07)
S17_32.S20_N: P1.21 U1.G4 | length 960.5
  Top Layer w6: U1.G4@2303.17,3287.4 v1(2322.84,3267.72)
  Top Layer w12: v1(3151.58,3322.05) P1.21@3212.78,3322.05
  Mid-Layer 1 w6: v1(2322.84,3267.72) 2342.52,3248.03 2460.63,3248.03 2480.31,3267.72 2677.17,3267.72 2696.85,3267.72 2714.79,3267.72 2716.54,3269.46 2993.87,3269.46 3051.18,3326.77 3129.92,3326.77 3134.64,3322.05 v1(3151.58,3322.05)
S17_32.S20_P: P1.23 U1.G3 | length 917.2
  Top Layer w6: U1.G3@2342.54,3287.4 v1(2362.21,3267.72)
  Top Layer w12: v1(3151.58,3353.55) P1.23@3212.78,3353.55
  Mid-Layer 1 w6: v1(2362.21,3267.72) 2381.89,3287.4 2677.17,3287.4 2696.85,3287.4 2712.6,3287.4 2716.54,3283.46 2988.07,3283.46 3045.38,3340.77 3129.92,3340.77 3142.7,3353.55 v1(3151.58,3353.55)
S17_32.S21_N: P1.27 U1.G5 | length 1018.8
  Top Layer w6: U1.G5@2263.8,3287.4 v1(2283.48,3267.72)
  Top Layer w12: v1(3151.58,3416.55) P1.27@3212.78,3416.55
  Mid-Layer 2 w6: v1(2283.48,3267.72) 2303.17,3287.4 2677.17,3287.4 2696.85,3287.4 2952.76,3287.4 3081.9,3416.55 v1(3151.58,3416.55)
S17_32.S21_P: P1.25 U1.G6 | length 1045.1
  Top Layer w6: U1.G6@2224.43,3287.4 v1(2244.11,3267.72)
  Top Layer w12: v1(3151.58,3385.05) P1.25@3212.78,3385.05
  MidLayer3 w6: v1(2244.11,3267.72) 2263.8,3287.4 2677.17,3287.4 2696.85,3287.4 2952.76,3287.4 3050.4,3385.05 v1(3151.58,3385.05)
S17_32.S22_N: P1.29 U1.H3 | length 940.7
  Top Layer w6: U1.H3@2342.54,3326.77 v1(2362.22,3307.09)
  Top Layer w12: v1(3151.58,3448.03) P1.29@3212.78,3448.03
  Mid-Layer 1 w6: v1(2362.22,3307.09) 2677.17,3307.09 2706.69,3307.09 2724.63,3307.09 2726.38,3308.83 2962.38,3308.83 3106.3,3452.76 3129.92,3452.76 3134.64,3448.03 v1(3151.58,3448.03)
S17_32.S22_P: P1.31 U1.H4 | length 992.5
  Top Layer w6: U1.H4@2303.17,3326.77 v1(2322.85,3307.09)
  Top Layer w12: v1(3151.58,3479.53) P1.31@3212.78,3479.53
  Mid-Layer 1 w6: v1(2322.85,3307.09) 2342.54,3326.77 2677.17,3326.77 2706.69,3326.77 2722.44,3326.77 2726.38,3322.83 2956.58,3322.83 3100.5,3466.76 3129.92,3466.76 3142.7,3479.53 v1(3151.58,3479.53)
S17_32.S23_N: P1.35 U1.L5 | length 1005.8
  Top Layer w6: U1.L5@2263.8,3444.88 v1(2283.48,3464.57)
  Top Layer w12: v1(3151.58,3542.55) P1.35@3212.78,3542.55
  Mid-Layer 2 w6: v1(2874.02,3484.25) 2893.7,3503.94 3090.55,3503.94 3129.16,3542.55 v1(3151.58,3542.55)
  Bottom Layer w6: v1(2283.48,3464.57) 2303.17,3484.25 2393.32,3484.25 2399.57,3478 2584.99,3478 2598.43,3464.57 2677.17,3464.57 2696.85,3464.57 2854.33,3464.57 v1(2874.02,3484.25)
S17_32.S23_P: P1.33 U1.L6 | length 1015.8
  Top Layer w6: U1.L6@2224.43,3444.88 v1(2244.11,3464.57)
  Top Layer w12: v1(3151.58,3511.03) P1.33@3212.78,3511.03
  MidLayer3 w6: v1(2244.11,3464.57) 2263.8,3484.25 2578.74,3484.25 2598.43,3503.94 2677.17,3503.94 2696.85,3503.94 3144.49,3503.94 v1(3151.58,3511.03)
S17_32.S24_N: P1.37 U1.J4 | length 1012
  Top Layer w6: U1.J4@2303.17,3366.14 v1(2322.85,3346.46)
  Top Layer w12: v1(3151.58,3574.02) P1.37@3212.78,3574.02
  Mid-Layer 1 w6: v1(2322.85,3346.46) 2342.54,3366.14 2677.17,3366.14 2695.7,3366.14 2713.64,3366.14 2715.39,3367.89 2875.76,3367.89 3081.89,3574.02 v1(3151.58,3574.02)
S17_32.S24_P: P1.39 U1.J5 | length 1067.2
  Top Layer w6: U1.J5@2263.8,3366.14 v1(2283.48,3346.46)
  Top Layer w12: v1(3151.58,3605.52) P1.39@3212.78,3605.52
  Mid-Layer 1 w6: v1(2283.48,3346.46) 2322.85,3385.83 2677.17,3385.83 2695.7,3385.83 2711.45,3385.83 2715.39,3381.89 2869.96,3381.89 3094.52,3606.45 v1@3150.65,3606.45
S17_32.S25_N: P1.43 U1.J2 | length 1114.3
  Top Layer w6: U1.J2@2381.91,3366.14 2401.59,3346.46 2618.11,3346.46 2683.07,3346.46 2706.69,3346.46 2715.55,3346.46 ; 2715.65,3346.46 2719.49,3350.3 2779.43,3350.3 2834.65,3405.51 v1(2834.65,3425.2)
  Top Layer w12: v1(3151.58,3825.98) P1.43@3212.78,3825.98
  Mid-Layer 1 w6: v1(2834.65,3425.2) 2854.2,3425.2 3073,3644 3073,3755.27 3143.72,3825.98 v1(3151.58,3825.98)
S17_32.S25_P: P1.41 U1.J1 | length 1037.3
  Top Layer w6: U1.J1@2421.28,3366.14 2667.32,3366.14 2683.07,3366.14 2706.69,3366.14 2715.65,3366.14 2719.49,3362.3 2752.06,3362.3 v1(2795.28,3405.51)
  Top Layer w12: v1(3151.58,3794.48) P1.41@3212.78,3794.48
  Mid-Layer 1 w6: v1(2795.28,3405.51) 2854.31,3405.51 3087,3638.2 3087,3749.47 3132.02,3794.48 v1(3151.58,3794.48)
S17_32.S26_N: P1.45 U1.L4 | length 1287.1
  Top Layer w6: U1.L4@2303.15,3444.88 v1(2322.84,3464.57)
  Top Layer w12: v1(3151.58,3857.47) P1.45@3212.78,3857.47
  Mid-Layer 2 w6: v1(2322.84,3464.57) 2342.52,3484.25 2381.89,3484.25 2401.57,3464.57 2627.95,3464.57 2667.32,3503.94 2677.17,3503.94 2696.85,3503.94 2785.43,3503.94 2805.12,3523.62 2805.12,3848.43 2814.16,3857.47 v1(3151.58,3857.47)
S17_32.S26_P: P1.47 U1.L3 | length 1273.3
  Top Layer w6: U1.L3@2342.54,3444.88 v1(2362.22,3464.57)
  Top Layer w12: v1(3151.58,3888.97) P1.47@3212.78,3888.97
  Mid-Layer 1 w6: v1(2362.22,3464.57) 2677.16,3464.57 2696.85,3464.57 2795.28,3464.57 2805.12,3474.41 2805.12,3848.43 2814.96,3858.27 3070.87,3858.27 3101.57,3888.97 v1(3151.58,3888.97)
S17_32.S27_N: P1.51 U1.M3 | length 1276.3
  Top Layer w6: U1.M3@2342.54,3484.25 v1(2362.22,3503.94)
  Top Layer w12: v1(3151.58,3951.97) P1.51@3212.78,3951.97
  Mid-Layer 1 w6: v1(2362.22,3503.94) 2381.91,3523.62 2677.17,3523.62 2696.85,3523.62 2712.6,3523.62 2716.54,3519.69 2724.69,3519.69 2751,3546 2751,3902.8 2790.2,3942 3133,3942 3142.97,3951.97 v1(3151.58,3951.97)
S17_32.S27_P: P1.49 U1.M4 | length 1321.9
  Top Layer w6: U1.M4@2303.17,3484.25 v1(2322.85,3503.94)
  Top Layer w12: v1(3151.58,3920.47) P1.49@3212.78,3920.47
  Mid-Layer 1 w6: v1(2322.85,3503.94) 2342.54,3484.25 2539.37,3484.25 2559.06,3503.94 2677.17,3503.94 2696.85,3503.94 2714.79,3503.94 2716.54,3505.68 2730.48,3505.68 2765,3540.2 2765,3897 2796,3928 3133,3928 3140.53,3920.47 v1(3151.58,3920.47)
S17_32.S28_N: P1.53 U1.M6 | length 1402.7
  Top Layer w6: U1.M6@2224.43,3484.25 v1(2244.11,3503.94)
  Top Layer w12: v1(3151.58,3983.45) P1.53@3212.78,3983.45
  MidLayer3 w6: v1(2244.11,3503.94) 2263.8,3523.62 2677.17,3523.62 2696.85,3523.62 2716.54,3523.62 2736.22,3543.31 2736.22,3897.64 2814.96,3976.38 3031.5,3976.38 3038.57,3983.45 v1(3151.58,3983.45)
S17_32.S28_P: P1.55 U1.M5 | length 1376.4
  Top Layer w6: U1.M5@2263.8,3484.25 v1(2283.48,3503.94)
  Top Layer w12: v1(3151.58,4014.95) P1.55@3212.78,4014.95
  Mid-Layer 2 w6: v1(2283.48,3503.94) 2303.17,3523.62 2677.17,3523.62 2696.85,3523.62 2716.54,3523.62 2736.22,3543.31 2736.22,3897.64 2814.96,3976.38 3031.5,3976.38 3070.07,4014.95 v1(3151.58,4014.95)
S17_32.S29_N: P1.59 U1.N5 | length 1374.6
  Top Layer w6: U1.N5@2263.8,3523.62 v1(2283.48,3543.31)
  Top Layer w12: v1(3151.58,4077.95) P1.59@3212.78,4077.95
  Mid-Layer 1 w6: v1(2283.48,3543.31) 2303.17,3562.99 2677.17,3562.99 2696.85,3562.99 2716.54,3582.68 2716.54,3917.32 2795.28,3996.06 3011.81,3996.06 3093.7,4077.95 v1(3151.58,4077.95)
S17_32.S29_P: P1.57 U1.N4 | length 1322.2
  Top Layer w6: U1.N4@2303.17,3523.62 v1(2322.85,3543.31)
  Top Layer w12: v1(3151.58,4046.45) P1.57@3212.78,4046.45
  Mid-Layer 2 w6: v1(2322.85,3543.31) 2342.54,3562.99 2677.17,3562.99 2696.85,3562.99 2716.54,3582.68 2716.54,3917.32 2795.28,3996.06 3011.81,3996.06 3062.2,4046.45 v1(3151.58,4046.45)
S17_32.S30_N: P1.61 U1.P6 | length 1445.3
  Top Layer w6: U1.P6@2224.43,3562.99 v1(2244.11,3582.68)
  Top Layer w12: v1(3151.58,4109.43) P1.61@3212.78,4109.43
  MidLayer3 w6: v1(2244.11,3582.68) 2263.78,3602.35 2263.78,3976.38 2263.78,3996.06 2283.46,4015.75 2657.48,4015.75 2716.54,4074.8 2972.44,4074.8 3007.07,4109.43 v1(3151.58,4109.43)
S17_32.S30_P: P1.63 U1.R6 | length 1419
  Top Layer w6: U1.R6@2224.43,3602.36 v1(2244.11,3622.05)
  Top Layer w12: v1(3151.58,4140.93) P1.63@3212.78,4140.93
  Mid-Layer 2 w6: v1(2244.11,3622.05) 2263.78,3641.72 2263.78,3976.38 2263.78,3996.06 2283.46,4015.75 2657.48,4015.75 2716.54,4074.8 2972.44,4074.8 3038.57,4140.93 v1(3151.58,4140.93)
S17_32.S31_N: P1.67 U1.T8 | length 1588.3
  Top Layer w6: U1.T8@2145.69,3641.73 v1(2165.37,3661.42)
  Top Layer w12: v1(3151.58,4203.93) P1.67@3212.78,4203.93
  Mid-Layer 1 w6: v1(2165.37,3661.42) 2165.37,3976.36 ; 2165.35,3976.38 2165.35,3996.06 2165.35,4011.81 2169.29,4015.75 2169.29,4157.59 2206.7,4195 3129,4195 3137.93,4203.93 v1(3151.58,4203.93)
S17_32.S31_P: P1.65 U1.R8 | length 1611.6
  Top Layer w6: U1.R8@2145.69,3602.36 v1(2165.37,3622.05)
  Top Layer w12: v1(3151.58,4172.43) P1.65@3212.78,4172.43
  Mid-Layer 1 w6: v1(2165.37,3622.05) 2185.04,3641.72 2185.04,3976.38 2185.04,3996.06 2185.04,4014 2183.29,4015.75 2183.29,4151.8 2212.5,4181 3129,4181 3137.57,4172.43 v1(3151.58,4172.43)
S17_32.S32_N: P1.69 U1.N8 | length 1796.4
  Top Layer w6: U1.N8@2145.69,3523.62 v1(2165.37,3543.31)
  Top Layer w12: v1(3151.58,4235.42) P1.69@3212.78,4235.42
  Mid-Layer 1 w6: v1(2165.37,3543.31) 2145.67,3563.01 2145.67,3976.38 2145.67,3996.06 2145.67,4192.91 2219.67,4266.92 3095.29,4266.92 3126.79,4235.42 v1(3151.58,4235.42)
S17_32.S32_P: P1.71 U1.P8 | length 1744
  Top Layer w6: U1.P8@2145.69,3562.99 v1(2165.37,3582.68)
  Top Layer w12: v1(3151.58,4266.92) P1.71@3212.78,4266.92
  Mid-Layer 2 w6: v1(2165.37,3582.68) 2145.67,3602.38 2145.67,3976.38 2145.67,3996.06 2145.67,4192.91 2219.76,4267 v1@3151.58,4267
S33_48.S33_N: P2.11 U1.E10 | length 2194.2
  Top Layer w6: v1(2047.26,3188.98) U1.E10@2066.95,3208.66
  Top Layer w12: P2.11@412.78,3164.58 v1(473.98,3164.58)
  Mid-Layer 1 w6: v1(473.98,3164.58) 496.95,3164.58 551.18,3110.35 551.18,3031.5 767.72,2814.96 1988.19,2814.96 2009.62,2836.39 2009.62,2858.27 2007.87,2860.02 2007.87,2877.95 2007.87,2893.7 2007.87,3031.5 2027.56,3051.18 2027.56,3169.27 v1(2047.26,3188.98)
S33_48.S33_P: P2.9 U1.D10 | length 2179.8
  Top Layer w6: v1(2047.26,3149.61) U1.D10@2066.95,3169.29
  Top Layer w12: P2.9@412.78,3133.08 v1(473.98,3133.08)
  Mid-Layer 1 w6: v1(473.98,3133.08) 508.65,3133.08 537.18,3104.55 537.18,3025.7 761.92,2800.96 1993.99,2800.96 2023.62,2830.59 2023.62,2858.27 2027.56,2862.2 2027.56,2877.95 2027.56,2893.7 2027.56,3031.5 2066.93,3070.87 2066.93,3129.94 v1(2047.26,3149.61)
S33_48.S34_N: P2.13 U1.F17 | length 1419
  Top Layer w6: P2.13@412.78,3196.07 481.07,3196.07 490.82,3205.82 787.4,3205.82 813.78,3232.19 1502.95,3232.19 1506.8,3228.35 1515.75,3228.35 1535.43,3228.35 1771.67,3228.35 U1.F17@1791.36,3248.03 ; 1539.37,3228.35 1555.12,3228.35
S33_48.S34_P: P2.15 U1.F18 | length 1400.9
  Top Layer w6: P2.15@412.78,3227.57 482.43,3227.57 492.18,3217.82 782.43,3217.82 808.81,3244.19 1502.95,3244.19 1506.79,3248.03 ; 1506.89,3248.03 1515.75,3248.03 1535.43,3248.03 1584.66,3248.03 ; 1539.37,3248.03 1584.65,3248.03 ; U1.F18@1751.99,3248.03 1584.66,3248.03
S33_48.S35_N: P2.19 U1.F11 | length 1764.4
  Top Layer w6: v1(2007.89,3228.35) U1.F11@2027.58,3248.03
  Top Layer w12: P2.19@412.78,3290.57 v1(473.98,3290.57)
  Mid-Layer 2 w6: v1(473.98,3290.57) 528.33,3290.57 708.66,3110.24 1515.75,3110.24 1535.43,3110.24 1574.8,3110.24 1633.86,3169.29 1979.33,3169.29 1988.19,3178.15 1988.19,3208.64 v1(2007.89,3228.35)
S33_48.S35_P: P2.17 U1.E11 | length 1717.2
  Top Layer w6: v1(2007.89,3188.98) U1.E11@2027.58,3208.66
  Top Layer w12: P2.17@412.78,3259.07 v1(473.98,3259.07)
  MidLayer3 w6: v1(473.98,3259.07) 559.83,3259.07 708.66,3110.24 1515.75,3110.24 1535.43,3110.24 1574.8,3110.24 1633.86,3169.29 1988.21,3169.29 v1(2007.89,3188.98)
S33_48.S36_N: P2.21 U1.H17 | length 1416.8
  Top Layer w6: P2.21@412.78,3322.05 481.07,3322.05 490.82,3331.8 783.13,3331.8 804,3310.93 1502.95,3310.93 1506.8,3307.09 1515.75,3307.09 1535.43,3307.09 1771.67,3307.09 U1.H17@1791.36,3326.77 ; 1539.37,3307.09 1555.12,3307.09
S33_48.S36_P: P2.23 U1.H16 | length 1448.4
  Top Layer w6: P2.23@412.78,3353.55 482.43,3353.55 492.18,3343.8 788.1,3343.8 808.97,3322.93 1502.95,3322.93 1506.79,3326.77 ; 1506.89,3326.77 1515.75,3326.77 1535.43,3326.77 v1(1584.65,3326.77) ; v1(1811.04,3346.46) U1.H16@1830.73,3326.77
  Mid-Layer 1 w6: v1@1584.65,3326.77 1751.77,3326.77 1771.46,3346.46 v1(1811.04,3346.46)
